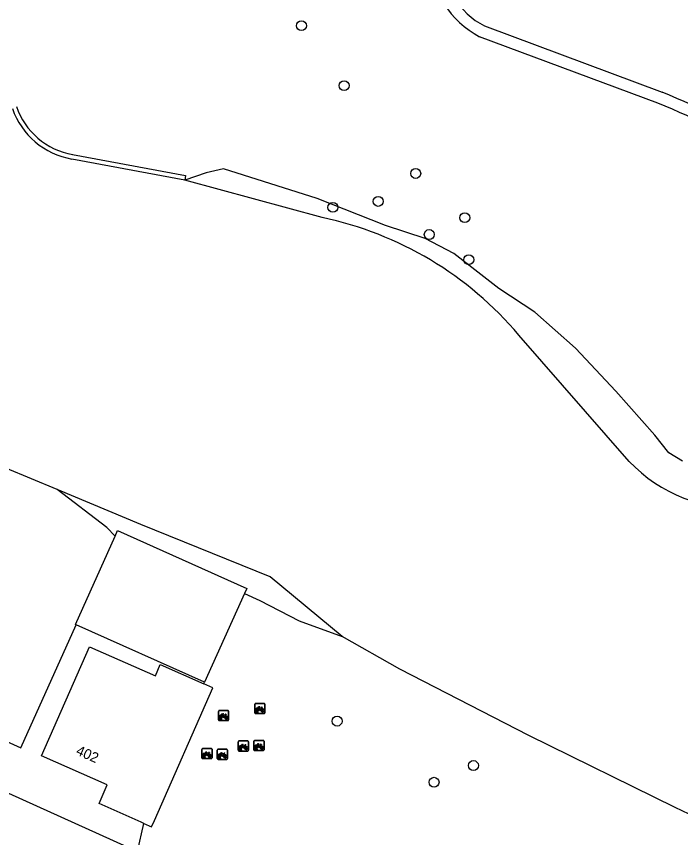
# Model space of a CAD drawing. Extents: x 155640 to 156810, y 382822 to 384046.
# Drawn here: x 155825.1 to 155890.7, y 383682.9 to 383764 of the extents above; entities that cross this region are included whole.
import ezdxf

# ---------------------------------------------------------------- set-up
doc = ezdxf.new("R2010")
doc.units = 0
for name, color, linetype in [('IMGEO_Boom', 7, 'Continuous'), ('IMGEO_Fietsenrek', 7, 'Continuous'), ('IMGEO_Groenvoorziening', 7, 'Continuous'), ('IMGEO_Kademuur', 7, 'Continuous'), ('IMGEO_Meer_plas_ven_vijver', 7, 'Continuous'), ('IMGEO_Pand', 7, 'Continuous'), ('IMGEO_Pand_nummerreeks', 7, 'Continuous'), ('IMGEO_Rijbaan_lokaal_open', 7, 'Continuous'), ('IMGEO_Voetpad_halfverhard', 7, 'Continuous'), ('IMGEO_Voetpad_open', 7, 'Continuous')]:
    doc.layers.add(name, color=color, linetype=linetype)

msp = doc.modelspace()

# ---------------------------------------------------------------- linework, layer by layer
at = {"layer": 'IMGEO_Boom'}
for centre in [(155853.276, 383763.124), (155857.488, 383757.203), (155864.562, 383748.526), (155856.374, 383745.178), (155860.854, 383745.768), (155869.41, 383744.157), (155865.897, 383742.496), (155869.802, 383740.01), (155856.796, 383694.428), (155870.262, 383690.04), (155866.373, 383688.39)]:
    msp.add_circle(centre, 0.489, dxfattribs=at)
at = {"layer": 'IMGEO_Fietsenrek'}
for p, q in [((155848.742, 383696.176), (155849.583, 383696.176)), ((155849.583, 383696.176), (155848.742, 383696.176)), ((155845.079, 383694.552), (155845.079, 383695.393)), ((155845.079, 383695.393), (155845.079, 383694.552)), ((155845.154, 383695.477), (155845.995, 383695.477)), ((155845.995, 383695.477), (155845.154, 383695.477)), ((155846.079, 383695.402), (155846.079, 383694.561)), ((155846.079, 383694.561), (155846.079, 383695.402)), ((155848.667, 383695.251), (155848.667, 383696.092)), ((155848.667, 383696.092), (155848.667, 383695.251)), ((155848.794, 383695.26), (155848.833, 383695.42)), ((155848.863, 383695.408), (155848.828, 383695.26)), ((155848.905, 383695.432), (155848.904, 383695.436)), ((155848.946, 383695.26), (155848.912, 383695.402)), ((155848.936, 383695.443), (155848.937, 383695.436)), ((155848.944, 383695.406), (155848.979, 383695.26)), ((155849.354, 383695.725), (155849.39, 383695.63)), ((155849.667, 383696.101), (155849.667, 383695.26)), ((155849.667, 383695.26), (155849.667, 383696.101)), ((155845.206, 383694.561), (155845.245, 383694.721)), ((155845.24, 383694.561), (155845.206, 383694.561)), ((155845.275, 383694.709), (155845.24, 383694.561)), ((155845.317, 383694.733), (155845.316, 383694.737)), ((155845.358, 383694.561), (155845.324, 383694.703)), ((155845.348, 383694.744), (155845.349, 383694.737)), ((155845.356, 383694.707), (155845.391, 383694.561)), ((155845.391, 383694.561), (155845.358, 383694.561)), ((155845.766, 383695.026), (155845.802, 383694.931)), ((155849.592, 383695.176), (155848.751, 383695.176)), ((155848.751, 383695.176), (155849.592, 383695.176)), ((155848.828, 383695.26), (155848.794, 383695.26)), ((155848.979, 383695.26), (155848.946, 383695.26)), ((155846.004, 383694.477), (155845.163, 383694.477)), ((155845.163, 383694.477), (155846.004, 383694.477)), ((155847.037, 383691.547), (155847.037, 383692.388)), ((155847.037, 383692.388), (155847.037, 383691.547)), ((155847.112, 383692.472), (155847.953, 383692.472)), ((155847.953, 383692.472), (155847.112, 383692.472)), ((155848.037, 383692.397), (155848.037, 383691.556)), ((155848.037, 383691.556), (155848.037, 383692.397)), ((155848.579, 383691.593), (155848.579, 383692.434)), ((155848.579, 383692.434), (155848.579, 383691.593)), ((155848.654, 383692.518), (155849.495, 383692.518)), ((155849.495, 383692.518), (155848.654, 383692.518)), ((155849.266, 383692.067), (155849.302, 383691.972)), ((155849.579, 383692.443), (155849.579, 383691.602)), ((155849.579, 383691.602), (155849.579, 383692.443)), ((155843.443, 383690.794), (155843.443, 383691.635)), ((155843.443, 383691.635), (155843.443, 383690.794)), ((155843.518, 383691.719), (155844.359, 383691.719)), ((155844.359, 383691.719), (155843.518, 383691.719)), ((155844.13, 383691.268), (155844.166, 383691.173)), ((155844.443, 383691.644), (155844.443, 383690.803)), ((155844.443, 383690.803), (155844.443, 383691.644)), ((155844.963, 383690.725), (155844.963, 383691.566)), ((155844.963, 383691.566), (155844.963, 383690.725)), ((155845.038, 383691.65), (155845.879, 383691.65)), ((155845.879, 383691.65), (155845.038, 383691.65)), ((155845.963, 383691.575), (155845.963, 383690.734)), ((155845.963, 383690.734), (155845.963, 383691.575)), ((155847.962, 383691.472), (155847.121, 383691.472)), ((155847.121, 383691.472), (155847.962, 383691.472)), ((155847.164, 383691.556), (155847.203, 383691.716)), ((155847.198, 383691.556), (155847.164, 383691.556)), ((155847.233, 383691.704), (155847.198, 383691.556)), ((155847.275, 383691.728), (155847.274, 383691.732)), ((155847.316, 383691.556), (155847.282, 383691.698)), ((155847.306, 383691.739), (155847.307, 383691.732)), ((155847.314, 383691.702), (155847.349, 383691.556)), ((155847.349, 383691.556), (155847.316, 383691.556)), ((155847.724, 383692.021), (155847.76, 383691.926)), ((155849.504, 383691.518), (155848.663, 383691.518)), ((155848.663, 383691.518), (155849.504, 383691.518)), ((155848.706, 383691.602), (155848.745, 383691.762)), ((155848.74, 383691.602), (155848.706, 383691.602)), ((155848.775, 383691.75), (155848.74, 383691.602)), ((155848.817, 383691.774), (155848.816, 383691.778)), ((155848.858, 383691.602), (155848.824, 383691.744)), ((155848.848, 383691.785), (155848.849, 383691.778)), ((155848.856, 383691.748), (155848.891, 383691.602)), ((155848.891, 383691.602), (155848.858, 383691.602)), ((155844.368, 383690.719), (155843.527, 383690.719)), ((155843.527, 383690.719), (155844.368, 383690.719)), ((155843.57, 383690.803), (155843.609, 383690.963)), ((155843.604, 383690.803), (155843.57, 383690.803)), ((155843.639, 383690.951), (155843.604, 383690.803)), ((155843.681, 383690.975), (155843.68, 383690.979)), ((155843.722, 383690.803), (155843.688, 383690.945)), ((155843.712, 383690.986), (155843.713, 383690.979)), ((155843.72, 383690.949), (155843.755, 383690.803)), ((155843.755, 383690.803), (155843.722, 383690.803)), ((155845.888, 383690.65), (155845.047, 383690.65)), ((155845.047, 383690.65), (155845.888, 383690.65)), ((155845.09, 383690.734), (155845.129, 383690.894)), ((155845.124, 383690.734), (155845.09, 383690.734)), ((155845.159, 383690.882), (155845.124, 383690.734)), ((155845.201, 383690.906), (155845.2, 383690.91)), ((155845.242, 383690.734), (155845.208, 383690.876)), ((155845.232, 383690.917), (155845.233, 383690.91)), ((155845.24, 383690.88), (155845.275, 383690.734)), ((155845.275, 383690.734), (155845.242, 383690.734)), ((155845.65, 383691.199), (155845.686, 383691.104))]:
    msp.add_line(p, q, dxfattribs=at)
for points in [[(155849.001, 383695.65), (155848.949, 383695.56), (155848.909, 383695.535), (155848.91, 383695.582), (155848.965, 383695.676)], [(155848.98, 383695.702), (155849.075, 383695.866), (155849.161, 383695.852), (155849.163, 383695.843), (155849.107, 383695.832), (155849.08, 383695.787), (155849.336, 383695.746)], [(155849.276, 383695.458), (155849.226, 383695.458), (155849.035, 383695.709), (155849.016, 383695.677)], [(155849.323, 383695.721), (155849.066, 383695.762), (155849.049, 383695.733), (155849.216, 383695.513), (155849.323, 383695.721)], [(155849.371, 383695.623), (155849.341, 383695.7), (155849.232, 383695.482), (155849.275, 383695.482)], [(155849.305, 383695.482), (155849.425, 383695.481), (155849.381, 383695.595)], [(155849.401, 383695.602), (155849.456, 383695.457), (155849.306, 383695.457)], [(155849.336, 383695.746), (155849.361, 383695.795), (155849.355, 383695.799), (155849.332, 383695.803), (155849.32, 383695.81), (155849.319, 383695.813), (155849.321, 383695.818), (155849.416, 383695.803), (155849.418, 383695.793), (155849.408, 383695.78), (155849.396, 383695.774), (155849.382, 383695.78), (155849.354, 383695.725)], [(155845.413, 383694.951), (155845.361, 383694.861), (155845.321, 383694.836), (155845.322, 383694.883), (155845.377, 383694.977)], [(155845.392, 383695.003), (155845.487, 383695.167), (155845.573, 383695.153), (155845.575, 383695.144), (155845.519, 383695.133), (155845.492, 383695.088), (155845.748, 383695.047)], [(155845.688, 383694.759), (155845.638, 383694.759), (155845.447, 383695.01), (155845.428, 383694.978)], [(155845.735, 383695.022), (155845.478, 383695.063), (155845.461, 383695.034), (155845.628, 383694.814), (155845.735, 383695.022)], [(155845.783, 383694.924), (155845.753, 383695.001), (155845.644, 383694.783), (155845.687, 383694.783)], [(155845.717, 383694.783), (155845.837, 383694.782), (155845.793, 383694.896)], [(155845.813, 383694.903), (155845.868, 383694.758), (155845.718, 383694.758)], [(155845.748, 383695.047), (155845.773, 383695.096), (155845.767, 383695.1), (155845.744, 383695.104), (155845.732, 383695.111), (155845.731, 383695.114), (155845.733, 383695.119), (155845.828, 383695.104), (155845.83, 383695.094), (155845.82, 383695.081), (155845.808, 383695.075), (155845.794, 383695.081), (155845.766, 383695.026)], [(155847.35, 383691.998), (155847.445, 383692.162), (155847.531, 383692.148), (155847.533, 383692.139), (155847.477, 383692.128), (155847.45, 383692.083), (155847.706, 383692.042)], [(155847.693, 383692.017), (155847.436, 383692.058), (155847.419, 383692.029), (155847.586, 383691.809), (155847.693, 383692.017)], [(155847.706, 383692.042), (155847.731, 383692.091), (155847.725, 383692.095), (155847.702, 383692.099), (155847.69, 383692.106), (155847.689, 383692.109), (155847.691, 383692.114), (155847.786, 383692.099), (155847.788, 383692.089), (155847.778, 383692.076), (155847.766, 383692.07), (155847.752, 383692.076), (155847.724, 383692.021)], [(155848.892, 383692.044), (155848.987, 383692.208), (155849.073, 383692.194), (155849.075, 383692.185), (155849.019, 383692.174), (155848.992, 383692.129), (155849.248, 383692.088)], [(155849.188, 383691.8), (155849.138, 383691.8), (155848.947, 383692.051), (155848.928, 383692.019)], [(155849.235, 383692.063), (155848.978, 383692.104), (155848.961, 383692.075), (155849.128, 383691.855), (155849.235, 383692.063)], [(155849.248, 383692.088), (155849.273, 383692.137), (155849.267, 383692.141), (155849.244, 383692.145), (155849.232, 383692.152), (155849.231, 383692.155), (155849.233, 383692.16), (155849.328, 383692.145), (155849.33, 383692.135), (155849.32, 383692.122), (155849.308, 383692.116), (155849.294, 383692.122), (155849.266, 383692.067)], [(155843.756, 383691.245), (155843.851, 383691.409), (155843.937, 383691.395), (155843.939, 383691.386), (155843.883, 383691.375), (155843.856, 383691.33), (155844.112, 383691.289)], [(155844.052, 383691.001), (155844.002, 383691.001), (155843.811, 383691.252), (155843.792, 383691.22)], [(155844.099, 383691.264), (155843.842, 383691.305), (155843.825, 383691.276), (155843.992, 383691.056), (155844.099, 383691.264)], [(155844.147, 383691.166), (155844.117, 383691.243), (155844.008, 383691.025), (155844.051, 383691.025)], [(155844.112, 383691.289), (155844.137, 383691.338), (155844.131, 383691.342), (155844.108, 383691.346), (155844.096, 383691.353), (155844.095, 383691.356), (155844.097, 383691.361), (155844.192, 383691.346), (155844.194, 383691.336), (155844.184, 383691.323), (155844.172, 383691.317), (155844.158, 383691.323), (155844.13, 383691.268)], [(155845.276, 383691.176), (155845.371, 383691.34), (155845.457, 383691.326), (155845.459, 383691.317), (155845.403, 383691.306), (155845.376, 383691.261), (155845.632, 383691.22)], [(155845.632, 383691.22), (155845.657, 383691.269), (155845.651, 383691.273), (155845.628, 383691.277), (155845.616, 383691.284), (155845.615, 383691.287), (155845.617, 383691.292), (155845.712, 383691.277), (155845.714, 383691.267), (155845.704, 383691.254), (155845.692, 383691.248), (155845.678, 383691.254), (155845.65, 383691.199)], [(155847.371, 383691.946), (155847.319, 383691.856), (155847.279, 383691.831), (155847.28, 383691.878), (155847.335, 383691.972)], [(155847.646, 383691.754), (155847.596, 383691.754), (155847.405, 383692.005), (155847.386, 383691.973)], [(155847.741, 383691.919), (155847.711, 383691.996), (155847.602, 383691.778), (155847.645, 383691.778)], [(155847.675, 383691.778), (155847.795, 383691.777), (155847.751, 383691.891)], [(155847.771, 383691.898), (155847.826, 383691.753), (155847.676, 383691.753)], [(155848.913, 383691.992), (155848.861, 383691.902), (155848.821, 383691.877), (155848.822, 383691.924), (155848.877, 383692.018)], [(155849.283, 383691.965), (155849.253, 383692.042), (155849.144, 383691.824), (155849.187, 383691.824)], [(155849.217, 383691.824), (155849.337, 383691.823), (155849.293, 383691.937)], [(155849.313, 383691.944), (155849.368, 383691.799), (155849.218, 383691.799)], [(155843.777, 383691.193), (155843.725, 383691.103), (155843.685, 383691.078), (155843.686, 383691.125), (155843.741, 383691.219)], [(155844.081, 383691.025), (155844.201, 383691.024), (155844.157, 383691.138)], [(155844.177, 383691.145), (155844.232, 383691), (155844.082, 383691)], [(155845.297, 383691.124), (155845.245, 383691.034), (155845.205, 383691.009), (155845.206, 383691.056), (155845.261, 383691.15)], [(155845.572, 383690.932), (155845.522, 383690.932), (155845.331, 383691.183), (155845.312, 383691.151)], [(155845.619, 383691.195), (155845.362, 383691.236), (155845.345, 383691.207), (155845.512, 383690.987), (155845.619, 383691.195)], [(155845.667, 383691.097), (155845.637, 383691.174), (155845.528, 383690.956), (155845.571, 383690.956)], [(155845.601, 383690.956), (155845.721, 383690.955), (155845.677, 383691.069)], [(155845.697, 383691.076), (155845.752, 383690.931), (155845.602, 383690.931)]]:
    msp.add_lwpolyline(points, dxfattribs=at)
for centre, radius, start, end in [((155848.745, 383696.098), 0.0779, 92.4484, 184.28452), ((155848.745, 383696.098), 0.0779, 92.4484, 184.28452), ((155849.589, 383696.098), 0.0779, 2.4484, 94.28452), ((155849.589, 383696.098), 0.0779, 2.4484, 94.28452), ((155845.157, 383695.399), 0.0779, 92.4484, 184.28452), ((155845.157, 383695.399), 0.0779, 92.4484, 184.28452), ((155846.001, 383695.399), 0.0779, 2.4484, 94.28452), ((155846.001, 383695.399), 0.0779, 2.4484, 94.28452), ((155848.907, 383695.561), 0.159, 62.67661, 242.13685), ((155848.907, 383695.561), 0.129, 63.31916, 238.90302), ((155848.887, 383695.432), 0.0499, 12.8025, 158.69338), ((155848.907, 383695.561), 0.159, 253.99666, 271.78671), ((155848.887, 383695.432), 0.0174, 12.8025, 163.45023), ((155848.907, 383695.561), 0.129, 253.41502, 269.02044), ((155848.907, 383695.561), 0.129, 283.60429, 43.43025), ((155848.907, 383695.561), 0.159, 283.5766, 46.60424), ((155849.434, 383695.477), 0.159, 113.3408, 178.32165), ((155849.434, 383695.477), 0.159, 187.0065, 105.77075), ((155849.434, 383695.477), 0.129, 113.92302, 177.95563), ((155849.434, 383695.477), 0.129, 188.67146, 104.58832), ((155845.157, 383694.555), 0.0779, 182.4484, 274.28452), ((155845.157, 383694.555), 0.0779, 182.4484, 274.28452), ((155845.319, 383694.862), 0.159, 62.67661, 242.13685), ((155845.319, 383694.862), 0.129, 63.31916, 238.90302), ((155845.299, 383694.733), 0.0499, 12.8025, 158.69338), ((155845.319, 383694.862), 0.159, 253.99666, 271.78671), ((155845.299, 383694.733), 0.0174, 12.8025, 163.45023), ((155845.319, 383694.862), 0.129, 253.41502, 269.02044), ((155845.319, 383694.862), 0.129, 283.60429, 43.43025), ((155845.319, 383694.862), 0.159, 283.5766, 46.60424), ((155845.846, 383694.778), 0.159, 113.3408, 178.32165), ((155845.846, 383694.778), 0.159, 187.0065, 105.77075), ((155845.846, 383694.778), 0.129, 113.92302, 177.95563), ((155845.846, 383694.778), 0.129, 188.67146, 104.58832), ((155846.001, 383694.555), 0.0779, 272.4484, 4.28452), ((155846.001, 383694.555), 0.0779, 272.4484, 4.28452), ((155848.745, 383695.254), 0.0779, 182.4484, 274.28452), ((155848.745, 383695.254), 0.0779, 182.4484, 274.28452), ((155849.589, 383695.254), 0.0779, 272.4484, 4.28452), ((155849.589, 383695.254), 0.0779, 272.4484, 4.28452), ((155847.115, 383692.394), 0.0779, 92.4484, 184.28452), ((155847.115, 383692.394), 0.0779, 92.4484, 184.28452), ((155847.959, 383692.394), 0.0779, 2.4484, 94.28452), ((155847.959, 383692.394), 0.0779, 2.4484, 94.28452), ((155848.657, 383692.44), 0.0779, 92.4484, 184.28452), ((155848.657, 383692.44), 0.0779, 92.4484, 184.28452), ((155848.819, 383691.903), 0.159, 62.67661, 242.13685), ((155849.501, 383692.44), 0.0779, 2.4484, 94.28452), ((155849.501, 383692.44), 0.0779, 2.4484, 94.28452), ((155843.521, 383691.641), 0.0779, 92.4484, 184.28452), ((155843.521, 383691.641), 0.0779, 92.4484, 184.28452), ((155843.683, 383691.104), 0.159, 62.67661, 242.13685), ((155844.365, 383691.641), 0.0779, 2.4484, 94.28452), ((155844.365, 383691.641), 0.0779, 2.4484, 94.28452), ((155845.041, 383691.572), 0.0779, 92.4484, 184.28452), ((155845.041, 383691.572), 0.0779, 92.4484, 184.28452), ((155845.885, 383691.572), 0.0779, 2.4484, 94.28452), ((155845.885, 383691.572), 0.0779, 2.4484, 94.28452), ((155847.115, 383691.55), 0.0779, 182.4484, 274.28452), ((155847.115, 383691.55), 0.0779, 182.4484, 274.28452), ((155847.277, 383691.857), 0.159, 62.67661, 242.13685), ((155847.277, 383691.857), 0.129, 63.31916, 238.90302), ((155847.257, 383691.728), 0.0499, 12.8025, 158.69338), ((155847.277, 383691.857), 0.159, 253.99666, 271.78671), ((155847.257, 383691.728), 0.0174, 12.8025, 163.45023), ((155847.277, 383691.857), 0.129, 253.41502, 269.02044), ((155847.277, 383691.857), 0.129, 283.60429, 43.43025), ((155847.277, 383691.857), 0.159, 283.5766, 46.60424), ((155847.804, 383691.773), 0.159, 113.3408, 178.32165), ((155847.804, 383691.773), 0.159, 187.0065, 105.77075), ((155847.804, 383691.773), 0.129, 113.92302, 177.95563), ((155847.804, 383691.773), 0.129, 188.67146, 104.58832), ((155847.959, 383691.55), 0.0779, 272.4484, 4.28452), ((155847.959, 383691.55), 0.0779, 272.4484, 4.28452), ((155848.657, 383691.596), 0.0779, 182.4484, 274.28452), ((155848.657, 383691.596), 0.0779, 182.4484, 274.28452), ((155848.819, 383691.903), 0.129, 63.31916, 238.90302), ((155848.799, 383691.774), 0.0499, 12.8025, 158.69338), ((155848.819, 383691.903), 0.159, 253.99666, 271.78671), ((155848.799, 383691.774), 0.0174, 12.8025, 163.45023), ((155848.819, 383691.903), 0.129, 253.41502, 269.02044), ((155848.819, 383691.903), 0.129, 283.60429, 43.43025), ((155848.819, 383691.903), 0.159, 283.5766, 46.60424), ((155849.346, 383691.819), 0.159, 113.3408, 178.32165), ((155849.346, 383691.819), 0.159, 187.0065, 105.77075), ((155849.346, 383691.819), 0.129, 113.92302, 177.95563), ((155849.346, 383691.819), 0.129, 188.67146, 104.58832), ((155849.501, 383691.596), 0.0779, 272.4484, 4.28452), ((155849.501, 383691.596), 0.0779, 272.4484, 4.28452), ((155843.521, 383690.797), 0.0779, 182.4484, 274.28452), ((155843.521, 383690.797), 0.0779, 182.4484, 274.28452), ((155843.683, 383691.104), 0.129, 63.31916, 238.90302), ((155843.663, 383690.975), 0.0499, 12.8025, 158.69338), ((155843.683, 383691.104), 0.159, 253.99666, 271.78671), ((155843.663, 383690.975), 0.0174, 12.8025, 163.45023), ((155843.683, 383691.104), 0.129, 253.41502, 269.02044), ((155843.683, 383691.104), 0.129, 283.60429, 43.43025), ((155843.683, 383691.104), 0.159, 283.5766, 46.60424), ((155844.21, 383691.02), 0.159, 113.3408, 178.32165), ((155844.21, 383691.02), 0.159, 187.0065, 105.77075), ((155844.21, 383691.02), 0.129, 113.92302, 177.95563), ((155844.21, 383691.02), 0.129, 188.67146, 104.58832), ((155844.365, 383690.797), 0.0779, 272.4484, 4.28452), ((155844.365, 383690.797), 0.0779, 272.4484, 4.28452), ((155845.041, 383690.728), 0.0779, 182.4484, 274.28452), ((155845.041, 383690.728), 0.0779, 182.4484, 274.28452), ((155845.203, 383691.035), 0.159, 62.67661, 242.13685), ((155845.203, 383691.035), 0.129, 63.31916, 238.90302), ((155845.183, 383690.906), 0.0499, 12.8025, 158.69338), ((155845.203, 383691.035), 0.159, 253.99666, 271.78671), ((155845.183, 383690.906), 0.0174, 12.8025, 163.45023), ((155845.203, 383691.035), 0.129, 253.41502, 269.02044), ((155845.203, 383691.035), 0.129, 283.60429, 43.43025), ((155845.203, 383691.035), 0.159, 283.5766, 46.60424), ((155845.73, 383690.951), 0.159, 113.3408, 178.32165), ((155845.73, 383690.951), 0.159, 187.0065, 105.77075), ((155845.73, 383690.951), 0.129, 113.92302, 177.95563), ((155845.73, 383690.951), 0.129, 188.67146, 104.58832), ((155845.885, 383690.728), 0.0779, 272.4484, 4.28452), ((155845.885, 383690.728), 0.0779, 272.4484, 4.28452)]:
    msp.add_arc(centre, radius, start, end, dxfattribs=at)
at = {"layer": 'IMGEO_Groenvoorziening'}
for points in [[(155890.916, 383720.102), (155889.566, 383720.942), (155888.179, 383722.677), (155884.314, 383727.037), (155880.334, 383731.265), (155876.334, 383734.824), (155872.78, 383737.16), (155868.318, 383740.625), (155865.494, 383742.11), (155861.562, 383743.371), (155854.814, 383746.051), (155845.563, 383748.973), (155843.854, 383748.588), (155841.756, 383747.872)], [(155834.869, 383712.698), (155834.06, 383713.546), (155829.139, 383717.292)], [(155847.664, 383707.031), (155849.173, 383706.345), (155853.055, 383704.321), (155857.284, 383702.786)]]:
    msp.add_lwpolyline(points, dxfattribs=at)
at = {"layer": 'IMGEO_Kademuur'}
for points in [[(155841.756, 383747.872), (155830.595, 383749.953)], [(155830.677, 383750.395), (155841.838, 383748.314), (155841.756, 383747.872)]]:
    msp.add_lwpolyline(points, dxfattribs=at)
for centre, radius, start, end in [((155831.871, 383757.406), 7.562, 199.09111, 260.28757), ((155831.874, 383757.415), 7.121, 198.52633, 260.32376)]:
    msp.add_arc(centre, radius, start, end, dxfattribs=at)
at = {"layer": 'IMGEO_Meer_plas_ven_vijver'}
for points in [[(155855.314, 383744.182), (155841.756, 383747.872)], [(155885.654, 383720.087), (155874.761, 383732.549)], [(155829.139, 383717.292), (155824.091, 383719.401), (155823.109, 383719.189), (155809.44, 383724.673), (155805.459, 383726.633)], [(155857.284, 383702.786), (155850.173, 383708.673), (155837.409, 383713.836), (155829.139, 383717.292)], [(155908.272, 383677.186), (155907.706, 383678.013), (155903.311, 383679.624), (155890.195, 383685.908), (155875.724, 383693.004), (155862.997, 383699.57), (155857.284, 383702.786)]]:
    msp.add_lwpolyline(points, dxfattribs=at)
for centre, radius, start, end in [((155848.072, 383710.005), 34.936, 40.1882, 78.03692), ((155896.424, 383730.257), 14.812, 223.35918, 273.91938)]:
    msp.add_arc(centre, radius, start, end, dxfattribs=at)
at = {"layer": 'IMGEO_Pand'}
for points in [[(155837.691, 383684.328), (155837.446, 383684.437), (155833.278, 383686.301), (155834.085, 383688.128), (155827.599, 383690.994), (155832.353, 383701.769), (155838.845, 383698.901), (155839.334, 383700.007), (155843.645, 383698.119)], [(155837.691, 383684.328), (155838.475, 383683.977), (155838.757, 383684.617), (155844.535, 383697.729), (155843.645, 383698.119)]]:
    msp.add_lwpolyline(points, dxfattribs=at)
at = {"layer": 'IMGEO_Rijbaan_lokaal_open'}
msp.add_lwpolyline([(155815.726, 383691.188), (155837.091, 383681.558)], dxfattribs=at)
at = {"layer": 'IMGEO_Voetpad_halfverhard'}
for points in [[(155871.342, 383763.097), (155888.91, 383756.552)], [(155888.49, 383755.474), (155870.87, 383762.038)]]:
    msp.add_lwpolyline(points, dxfattribs=at)
for centre, radius, start, end in [((155874.928, 383769.923), 8.868, 180.51322, 242.76892), ((155874.925, 383769.922), 7.708, 180.59306, 242.30386), ((155858.631, 383682.235), 80.249, 58.85399, 67.83233), ((155858.565, 383682.107), 79.235, 58.84869, 67.81009)]:
    msp.add_arc(centre, radius, start, end, dxfattribs=at)
at = {"layer": 'IMGEO_Voetpad_open'}
for points in [[(155834.869, 383712.698), (155835.114, 383713.244), (155847.889, 383707.531), (155847.664, 383707.031)], [(155831.019, 383703.945), (155830.95, 383703.976), (155834.869, 383712.698)], [(155847.664, 383707.031), (155843.714, 383698.272)], [(155815.726, 383691.188), (155817.64, 383695.365), (155825.556, 383691.789), (155831.019, 383703.945)], [(155843.714, 383698.272), (155831.019, 383703.945)], [(155843.645, 383698.119), (155843.714, 383698.272)], [(155837.091, 383681.558), (155837.691, 383684.328)]]:
    msp.add_lwpolyline(points, dxfattribs=at)

# ---------------------------------------------------------------- texts
at = {"layer": 'IMGEO_Pand_nummerreeks'}
msp.add_text('402', height=1, rotation=336.15923, dxfattribs=at).set_placement((155830.923, 383691.165))

doc.saveas('drawing.dxf')
